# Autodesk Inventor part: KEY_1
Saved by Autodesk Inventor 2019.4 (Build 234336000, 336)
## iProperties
Created: 2020-05
Part Number: KEY_1
Material: Generic
Document SubType Name: Modeling
Designer: Administrator
Density: 1 g/cm^3
Appearance: Default
Title: KEY_1
Author: Administrator
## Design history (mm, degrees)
feature "Body1"
body "Solid1"
